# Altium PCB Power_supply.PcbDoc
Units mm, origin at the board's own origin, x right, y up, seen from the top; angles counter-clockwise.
Board outline 53.02 x 38.23 mm, 2 copper layers (Top Layer, Bottom Layer), stack 0.871 mm thick; 14 components, 11 nets, 39 pads, 3 vias.
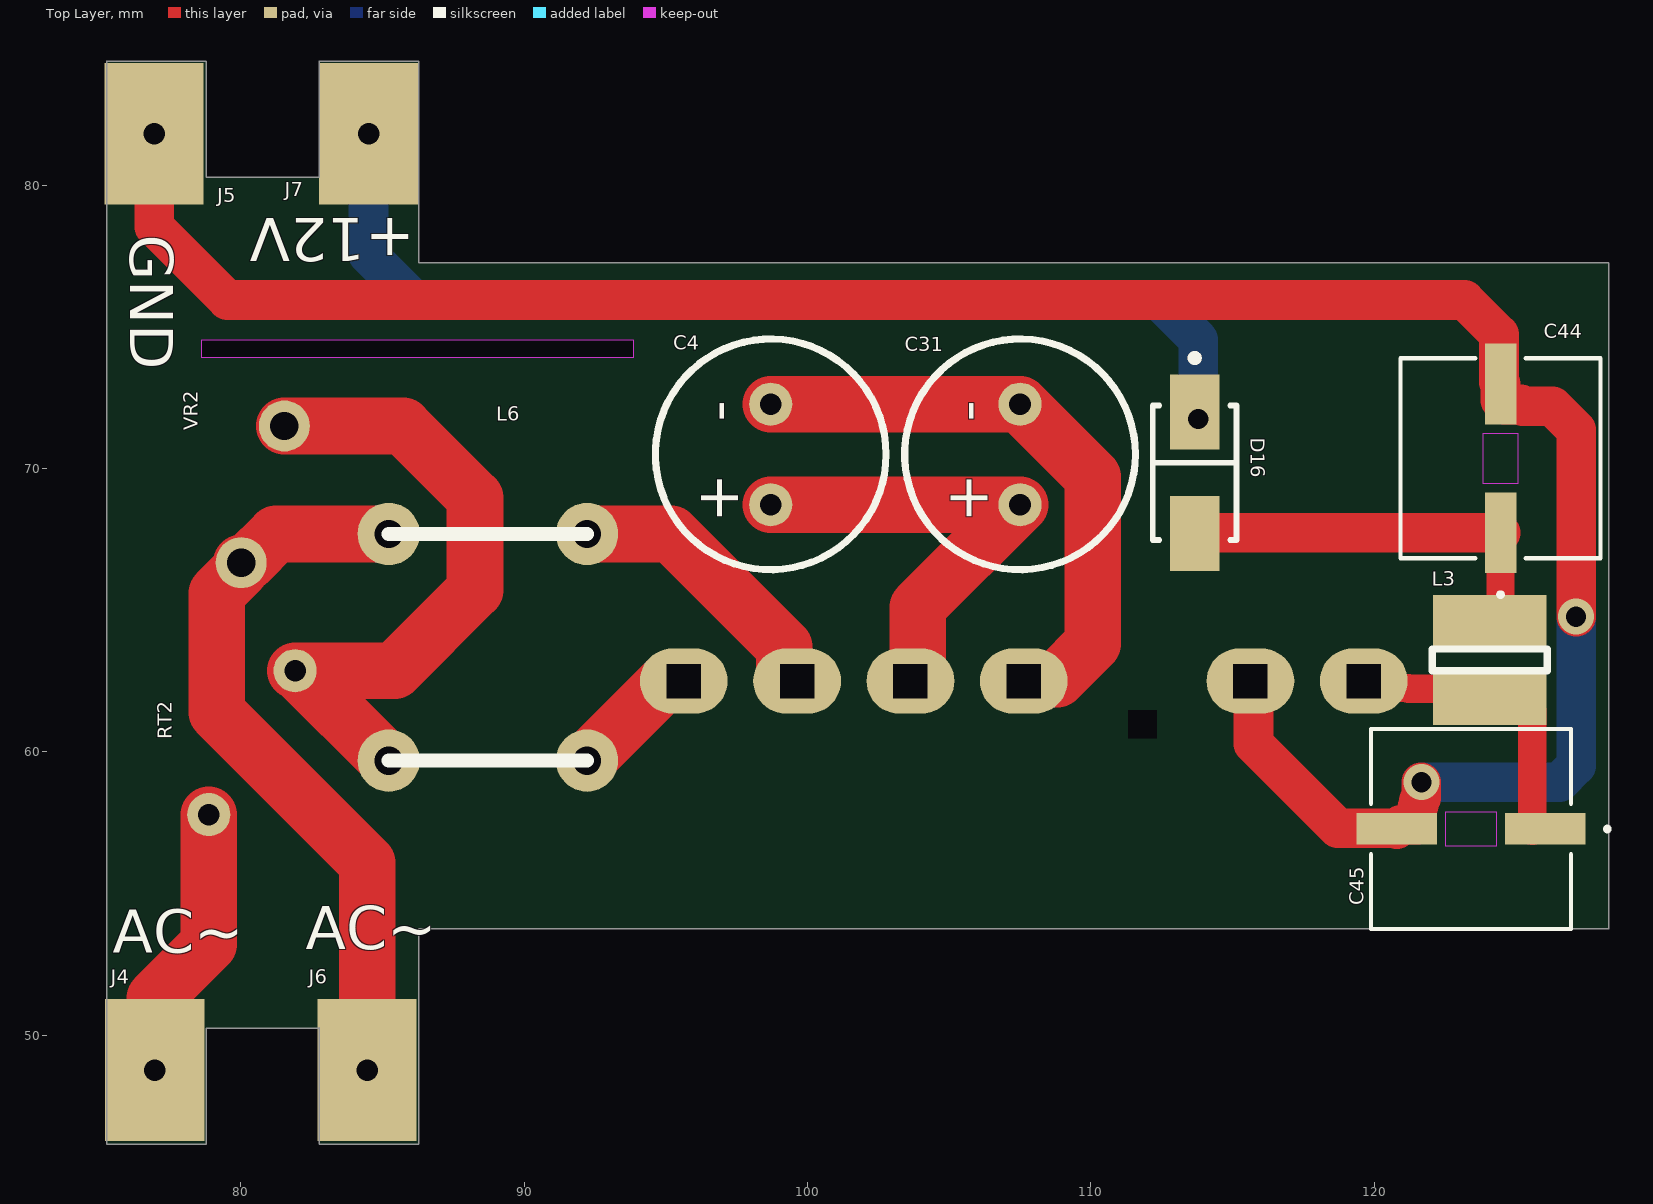
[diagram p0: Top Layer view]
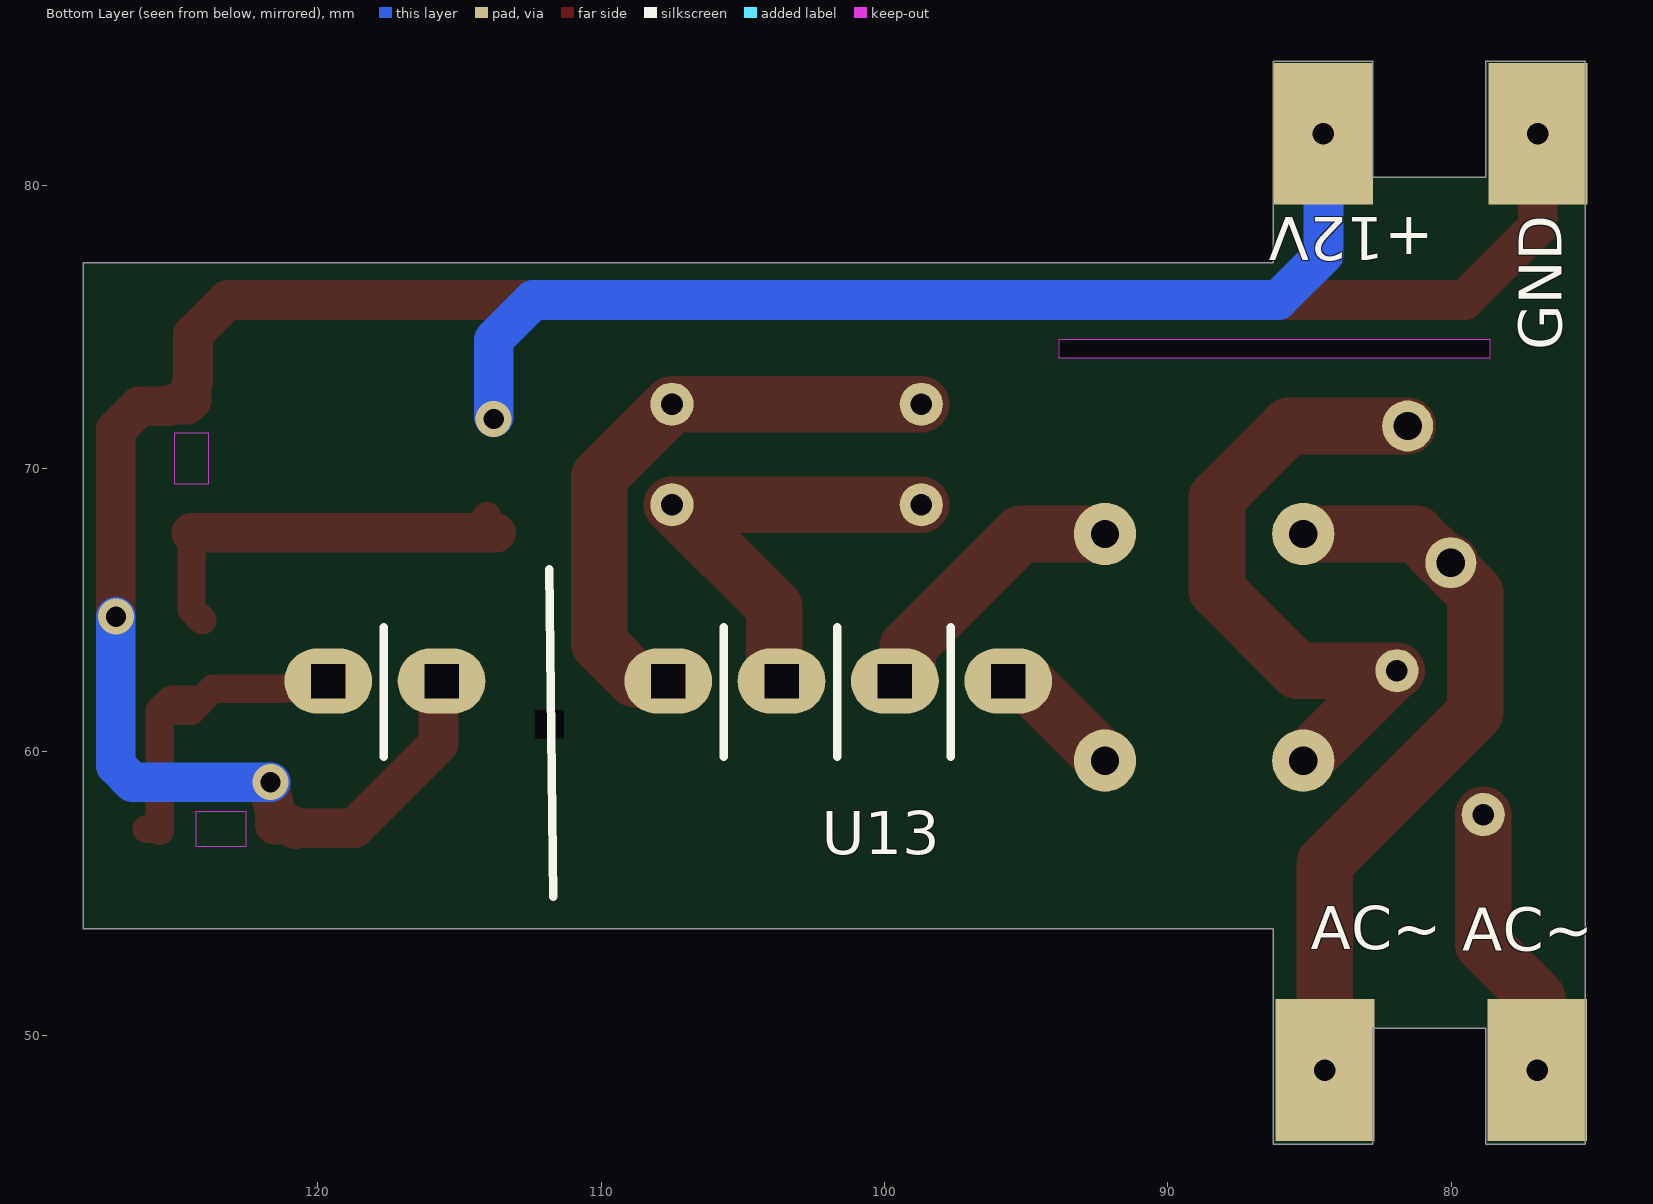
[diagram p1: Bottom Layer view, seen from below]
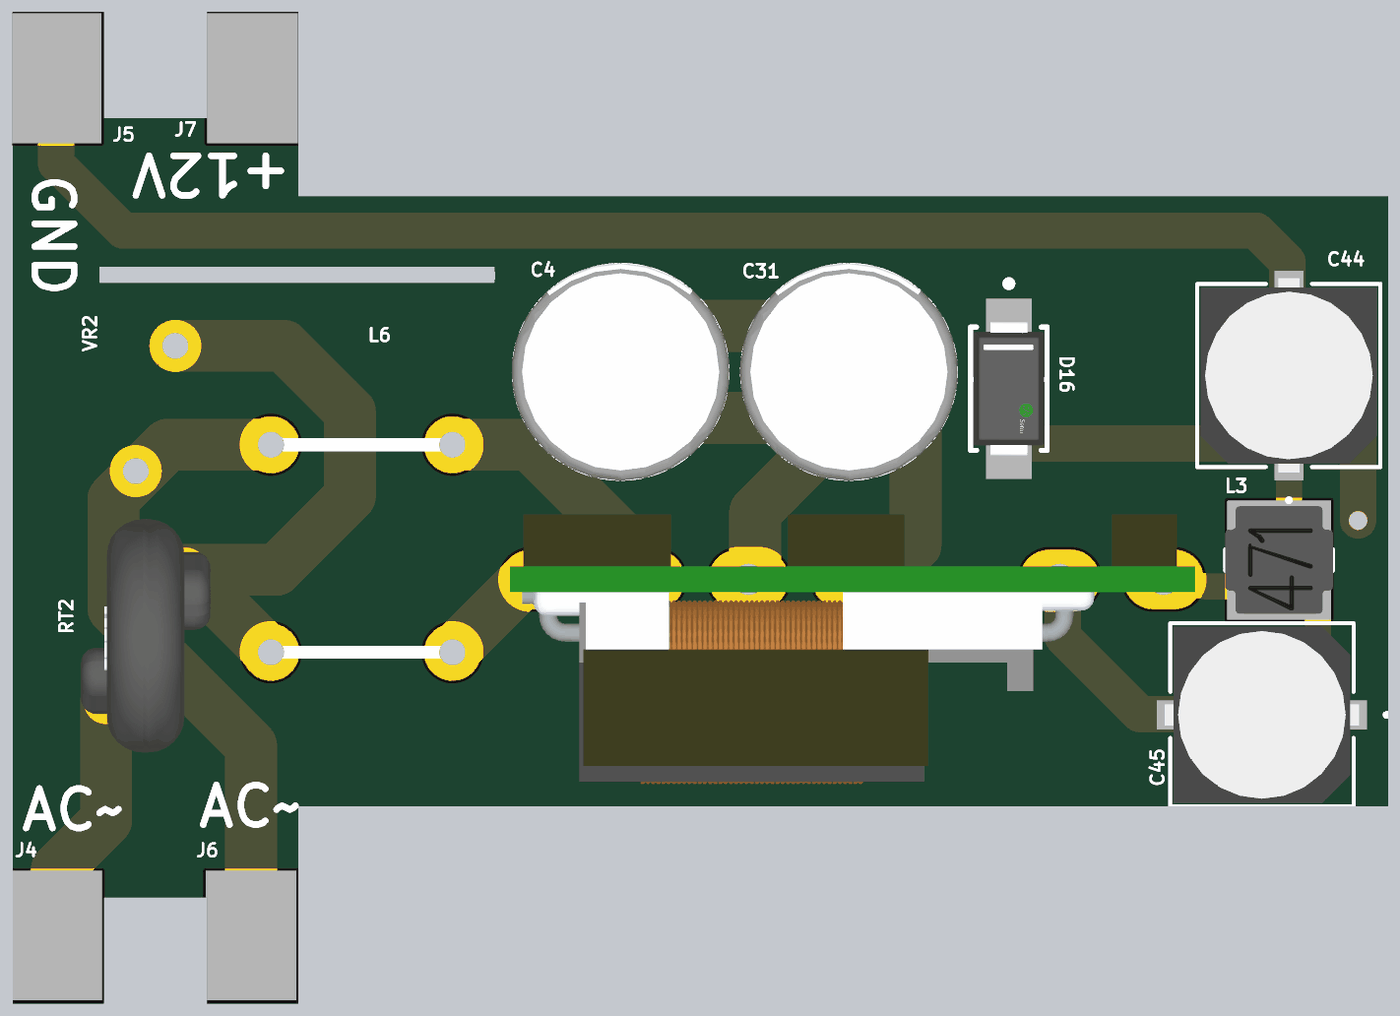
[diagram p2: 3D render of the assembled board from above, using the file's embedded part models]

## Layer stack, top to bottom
Top Solder: solder mask 0.0102, Solder Resist, Dk 3.5
Top Layer: signal copper 0.0356
Dielectric 1: dielectric 0.8, FR-4, Dk 4.8
Bottom Layer: signal copper 0.0356
Bottom Solder: solder mask 0.0102, Solder Resist, Dk 3.5

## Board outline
75.272,46.149 78.772,46.149 78.778,46.155 78.778,50.249 82.758,50.249 82.758,46.167 82.772,46.149 86.272,46.149 86.278,46.155 86.278,53.749 128.272,53.749 128.278,53.755 128.278,77.255 128.272,77.262 86.278,77.262 86.278,84.355 86.265,84.374 82.765,84.374 82.758,84.367 82.758,80.274 78.778,80.274 78.778,84.355 78.765,84.374 75.265,84.374 75.258,84.367
cut-out: 78.613,73.914 78.613,74.549 93.853,74.549 93.853,73.914

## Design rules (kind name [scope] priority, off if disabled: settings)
Clearance [All] p1: gap=0.254 ignorepadtopadclearanceinfootprint=FALSE
PolygonConnect [All] p1: connectstyle=Relief reliefconductorwidth=0.254 reliefentries=4 polygonreliefangle="90 Angle" airgapwidth=0.254
RoutingVias [All] p1: holewidth=0.711 width=1.27 viastyle="Through Hole" minholewidth=0.711 minwidth=1.27 maxholewidth=0.711 maxwidth=1.27
SolderMaskExpansion [All] p1: expansion=0.102 istentingtop=FALSE
Width [All] p1: maxlimit=3 minlimit=0.254 preferedwidth=1 minimp=50.000000 maximp=50.000000 favimp=50.000000
30 further rules are at their usual default settings.

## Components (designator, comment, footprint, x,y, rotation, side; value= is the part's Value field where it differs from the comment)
C4 "6.8uF 450V" CAPPOL_10x13 98.7,70.5 r90 top
C31 "6.8uF 450V" CAPPOL_10x13 107.5,70.5 r90 top locked
C44 "100uF 25V" CAP_A765EB_KEM-L 124.46,70.358 r90 top
C45 "330uF 25V" CAP_A765EB_KEM-L 123.419,57.277 r180 top
D16 "SS14" DO-214-AC 113.665,69.85 r90 top
J4 "Pad_CONN 3.5mm" Pad_conn_3.5x5mm 76.962,48.768 r90 top
J5 "Pad_CONN 3.5mm" Pad_conn_3.5x5mm 76.937,81.813 r90 top
J6 "Pad_CONN 3.5mm" Pad_conn_3.5x5mm 84.455,48.768 r90 top
J7 "Pad_CONN 3.5mm" Pad_conn_3.5x5mm 84.506,81.813 r90 top
L3 "2.2uH" Coil_4.5x4.5_mm 124.079,63.246 r90 top
L6 "10uH" "Common Mode Choke Inductor  30mH" 88.717,63.69 r270 top
RT2 "MF72 5D7" "MF72 XD-7" 80.391,60.325 r270 top
U13 "LS05-13B12R3" "YLPTEC LS05-13B12R3" 107.632,62.5 r0 bottom locked
VR2 "HEL 10D471K" HEL_7D561K 80.772,69.088 r90 top

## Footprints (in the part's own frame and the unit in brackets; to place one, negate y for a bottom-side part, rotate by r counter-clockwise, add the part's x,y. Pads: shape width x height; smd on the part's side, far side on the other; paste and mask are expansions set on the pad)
CAP_A765EB_KEM-L [mm]
  rect 2.843x1.113 smd paste+0 mask+0: 1(-2.625,0) 2(2.625,0)
  Keep-Out Layer region: -0.889,-0.607 -0.889,0.607 0.889,0.607 0.889,-0.607
  silkscreen extent -4.88,-3.53 3.53,3.53, body extent -3.75,-3.4 3.75,3.4, height 6.05
CAPPOL_10x13 [mil]
  round 60 hole 30: 1(-70,0) 2(69.68,0)
  silkscreen extent -160,-160 160,160, body extent -165,-165 165,165, height 598
Coil_4.5x4.5_mm [mm]
  rect 1.8x4 smd: 1(-1.397,0) 2(1.397,0)
  silkscreen extent -0.38,-2.03 0.38,2.03, body extent -2.07,-2.07 2.07,2.07, height 2.8
"Common Mode Choke Inductor  30mH" [mm] "Common Mode Choke Inductor  20mH For Filter Pitch 7*8mm"
  round 2.2 hole 1: 1(-4,-3.5) 2(-4,3.5) 3(4,-3.5) 4(4,3.5)
  silkscreen extent -4,-3.5 4,3.5, body extent -7.75,-5.5 7.75,5.5, height 17
DO-214-AC [mm]
  rect 2.65x1.75 smd paste+0 mask+0: 1(-2.15,0) 2(2.15,0)
  silkscreen extent -2.37,-1.48 4.17,1.48, body extent -3.57,-1.58 3.57,1.58, height 0.25
HEL_7D561K [mm] "HEL_7D561K"
  round 1.8 hole 1: 1(-2.413,0.762) 2(2.413,-0.762)
  body extent -4,-2.1 4,2.1, height 11
"MF72 XD-7" [mil]
  round 60 hole 30: 1(-100,60) 2(100,-60)
  body extent -177,-98 177,98, height 472
Pad_conn_3.5x5mm [mm] "Pad_conn_5x5mm"
  round 1.524 hole 0.762: 1(0,0)
  rect 5x3.5 smd: 1(0,0)
  rect 5x3.5 smd far side: 1(0,0)
"YLPTEC LS05-13B12R3" [mm] "YLPTEC LS05-13B12R322"
  oval 3.1x2.3 hole 1.2 square: 1(-12,0) 2(-8,0) 3(-4,0) 4(0,0) 5(8,0) 6(12,0)
  rect 0.5x0.7 hole 1 square: ""(4.191,1.524)
  silkscreen extent -9.97,-3.94 10.03,7.62, body extent -13.19,-2.5 13.21,7.9, height 2.5

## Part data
C4 C31: library part CAP-POLAR, "6.8uF 450V LOW ESR"
C44: library part CAP_POL_SMD, "100uF 25V SMD,D6.3xL5.4mm  RST100UF25V004​ /   KNSCHA"
C45: library part CAP_POL_SMD, "330uF 25V SMD,D6.3xL7.7mm  KNSCHA"
J4 J5 J6 J7: library part Klema_15_A
L3: library part Coil, "2.2uH 3A / 40mΩMAX  MPS MPL-AL4020-2R2"
L6: library part Drossel_Synphaze, "10uH  UU9.8 Common Mode Choke Inductor  /  / https://www.aliexpress.com/item/1005010443177841.html?spm=a2g0o.productlist.main.2.581f7bb894iQm9&algo_pvid=ef88ecc3-47f4-4459-8795-a7f2bc477caf&algo_exp_id=ef88ecc3-47f4-4459-8795-a7f2bc477caf-1&pdp_ext_f=%7B%22order%22%3A%22121%22%2C%22spu_best_type%22%3A%22price%22%2C%22eval%22%3A%221%22%2C%22fromPage%22%3A%22search%22%7D&pdp_npi=6%40dis%21UAH%21205.26%2196.09%21%21%2127.70%2112.97%21%402103973d17954349978863633e10a8%2112000052425269179%21sea%21UA%214339914066%21X%211%210%21n_tag%3A-29919%3Bd%3A9b83968a%3Bm03_new_user%3A-29895&curPageLogUid=TjiBi6yV6N5C&utparam-url=scene%3Asearch%7Cquery_from%3A%7Cx_object_id%3A1005010443177841%7C_p_origin_prod%3A"
RT2: library part RES-TEMP
VR2: library part MOV, "Metal Oxide Varistor  HEL 10D471K"

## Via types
v1: diameter 1.27, hole 0.711, Top Layer to Bottom Layer, tented both sides, 3 vias

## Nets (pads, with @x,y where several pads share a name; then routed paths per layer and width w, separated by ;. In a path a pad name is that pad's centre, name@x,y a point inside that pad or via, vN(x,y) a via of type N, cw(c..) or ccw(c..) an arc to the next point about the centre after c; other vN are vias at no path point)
NetC4_1: C4.1 C31.1 U13.3 | length 16.5
  Top Layer w2: C4.1 C31.1 103.886,65.108 U13.3@103.886,62.5
NetC4_2: C4.2 C31.2 U13.4 | length 21.3
  Top Layer w2: C4.2 C31.2 110.069,69.701 110.069,63.822 108.805,62.557 107.689,62.557 U13.4
NetC44_1: C44.1 D16.1 L3.2 | length 14.8
  Top Layer w1: D16.1 114.04,68.075 D16.1@114.04,68.326 ; L3.2 124.46,65.024 C44.1
  Top Layer w1.4: D16.1@113.698,67.733 C44.1
NetC44_2: C44.2 C45.2 J5.1 U13.5 | length 85.7
  Top Layer w1.4: J5.1@76.937,81.813 76.937,78.537 79.527,75.946 123.19,75.946 124.404,74.732 124.404,73.039 C44.2 124.46,72.405 124.604,72.261 125.182,72.261 125.242,72.201 126.293,72.201 127.127,71.367 v1(127.127,64.77) ; U13.5@115.632,61.925 115.739,61.818 115.739,60.283 118.72,57.302 C45.2@120.794,57.302 ; C45.2 120.937,57.421 121.515,57.421 121.515,58.037 121.576,58.097 121.576,58.279 121.666,58.37 v1(121.666,58.928)
  Bottom Layer w1.4: v1(121.666,58.928) 126.541,58.928 127.127,59.514 v1(127.127,64.77)
NetC45_1: C45.1 L3.1 U13.6 | length 12.4
  Top Layer w1: U13.6 119.881,62.251 121.2,62.251 121.221,62.23 123.698,62.23 124.479,61.449 125.179,61.449 L3.1@125.579,61.449 ; L3.1@124.479,61.849 125.179,61.849 L3.1@125.579,61.449 ; C45.1 125.65,57.277 125.579,57.206 L3.1@125.579,61.449
NetD16_2: D16.2 J7.1 | length 37.5
  Bottom Layer w1.4: J7.1@84.506,81.813 84.506,77.546 86.106,75.946 112.395,75.946 113.792,74.549 v1@113.792,71.819
  other v1: 113.792,71.746
NetJ4_1: J4.1 RT2.2 | length 9.8
  Top Layer w1: J4.1@76.962,48.768 76.962,51.308
  Top Layer w2: 76.962,51.308 78.867,53.213 RT2.2
NetJ6_1: J6.1 L6.1 VR2.1 | length 26.1
  Top Layer w2: J6.1@84.455,48.768 84.455,56.083 79.146,61.392 79.146,65.595 80.01,66.459 VR2.1 80.226,66.675 81.241,67.69 L6.1
NetL6_2: L6.2 U13.2 | length 10.1
  Top Layer w2: L6.2@92.271,67.69 95.19,67.69 99.175,63.705 99.175,62.639 99.313,62.5 U13.2
NetL6_3: L6.3 RT2.1 VR2.2 | length 23.2
  Top Layer w2: VR2.2 85.725,71.501 88.265,68.961 88.265,65.71 85.42,62.865 RT2.1 81.978,62.865 85.153,59.69 L6.3
NetL6_4: L6.4 U13.1 | length 4.5
  Top Layer w2: L6.4@92.255,59.728 94.97,62.443 95.575,62.443 U13.1
pads on no net: U13.

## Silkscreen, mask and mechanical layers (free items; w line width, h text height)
Top Overlay:
  text "+12V" at 86.131,78.842 h1.52 r180
  text "GND" at 76.098,78.257 h1.52 r270
  text "AC~" at 82.296,53.035 h1.52
  text "AC~" at 75.471,52.901 h1.52
Bottom Overlay:
  text "+12V" at 80.62,78.867 h1.52 r180
  text "GND" at 76.098,74.168 h1.52 r270
  text "AC~" at 84.949,53.024 h1.52
  text "AC~" at 79.604,52.984 h1.52
Mechanical 1:
  lines w0.013: 86.265,46.167 82.765,46.167 82.765,50.267 78.765,50.267 78.765,46.167 75.265,46.167 75.265,84.367 78.765,84.367 78.765,80.267 82.765,80.267 82.765,84.367 86.265,84.367 ; 75.272,46.155 78.772,46.155 78.772,50.255 82.772,50.255 82.772,46.155 86.272,46.155 86.272,53.755 128.272,53.755 128.272,77.255 86.272,77.255 86.272,84.355 82.772,84.355 82.772,80.255 78.772,80.255 78.772,84.355 75.272,84.355 75.272,46.155
  lines w0.254: 78.613,73.914 93.853,73.914 93.853,74.549 78.613,74.549 78.613,73.914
